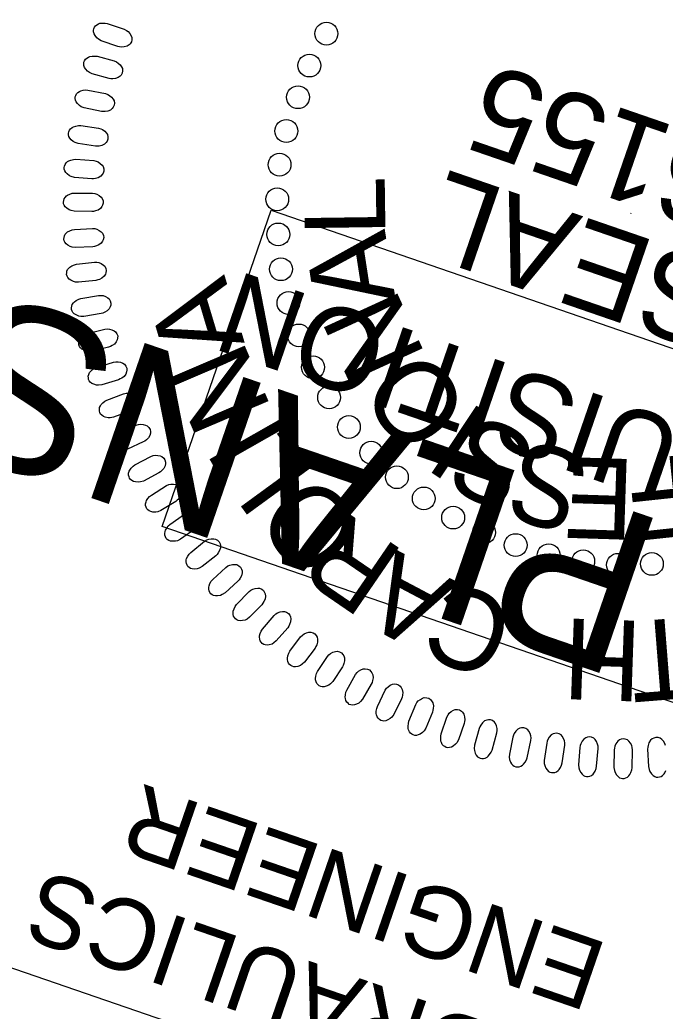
# Model space of a CAD drawing. Extents: x 479650 to 481768, y 492454 to 494037.
# Drawn here: x 479711.7 to 479757, y 493041.5 to 493111.2 of the extents above; entities that cross this region are included whole.
import ezdxf

# ---------------------------------------------------------------- set-up
doc = ezdxf.new("R2010")
doc.units = 0
for name, color, linetype in [('Sheet PE Seal Cell', 7, 'Continuous'), ('Sheet Plan CELL', 7, 'Continuous'), ('Sheet Sticker Incomplete CELL', 7, 'Continuous')]:
    doc.layers.add(name, color=color, linetype=linetype)

msp = doc.modelspace()

# ---------------------------------------------------------------- linework, layer by layer
at = {"layer": 'Sheet PE Seal Cell'}
msp.add_line((479754.607, 493097.561), (479754.623, 493097.605), dxfattribs=at)
for points in [[(479718.58, 493109.285), (479717.42, 493109.686), (479717.225, 493109.792), (479717.11, 493109.887), (479716.986, 493110.049), (479716.914, 493110.176), (479716.875, 493110.308), (479716.872, 493110.42), (479716.89, 493110.533), (479716.945, 493110.632), (479717.012, 493110.735), (479717.103, 493110.815), (479717.231, 493110.881), (479717.326, 493110.912), (479717.49, 493110.927), (479717.679, 493110.925), (479717.837, 493110.894), (479719.028, 493110.491), (479719.18, 493110.415), (479719.298, 493110.326), (479719.419, 493110.189), (479719.515, 493110.039), (479719.559, 493109.921), (479719.564, 493109.752), (479719.534, 493109.605), (479719.447, 493109.476), (479719.366, 493109.394), (479719.231, 493109.306), (479719.031, 493109.249), (479718.839, 493109.243), (479718.707, 493109.257)], [(479717.962, 493107.033), (479716.779, 493107.36), (479716.578, 493107.455), (479716.457, 493107.542), (479716.323, 493107.695), (479716.244, 493107.818), (479716.197, 493107.948), (479716.186, 493108.059), (479716.197, 493108.172), (479716.246, 493108.275), (479716.306, 493108.382), (479716.392, 493108.467), (479716.516, 493108.542), (479716.609, 493108.578), (479716.771, 493108.603), (479716.96, 493108.613), (479717.119, 493108.592), (479718.333, 493108.265), (479718.49, 493108.198), (479718.613, 493108.117), (479718.743, 493107.989), (479718.847, 493107.844), (479718.899, 493107.729), (479718.915, 493107.562), (479718.894, 493107.412), (479718.816, 493107.279), (479718.74, 493107.191), (479718.61, 493107.095), (479718.415, 493107.025), (479718.223, 493107.008), (479718.091, 493107.014)], [(479717.422, 493104.718), (479716.221, 493104.97), (479716.014, 493105.052), (479715.888, 493105.131), (479715.745, 493105.276), (479715.657, 493105.393), (479715.602, 493105.519), (479715.584, 493105.63), (479715.588, 493105.743), (479715.631, 493105.849), (479715.685, 493105.961), (479715.764, 493106.051), (479715.884, 493106.132), (479715.974, 493106.174), (479716.134, 493106.21), (479716.323, 493106.232), (479716.483, 493106.221), (479717.715, 493105.971), (479717.876, 493105.914), (479718.003, 493105.841), (479718.141, 493105.721), (479718.255, 493105.582), (479718.313, 493105.471), (479718.34, 493105.305), (479718.328, 493105.154), (479718.258, 493105.017), (479718.188, 493104.925), (479718.064, 493104.82), (479717.874, 493104.738), (479717.685, 493104.709), (479717.551, 493104.707)], [(479717.003, 493102.283), (479715.79, 493102.458), (479715.578, 493102.527), (479715.447, 493102.598), (479715.295, 493102.734), (479715.201, 493102.845), (479715.137, 493102.968), (479715.113, 493103.077), (479715.109, 493103.191), (479715.145, 493103.299), (479715.192, 493103.413), (479715.266, 493103.508), (479715.38, 493103.597), (479715.467, 493103.645), (479715.625, 493103.69), (479715.812, 493103.724), (479715.972, 493103.723), (479717.217, 493103.551), (479717.382, 493103.504), (479717.513, 493103.44), (479717.658, 493103.328), (479717.781, 493103.197), (479717.846, 493103.09), (479717.883, 493102.925), (479717.881, 493102.775), (479717.82, 493102.633), (479717.756, 493102.536), (479717.639, 493102.425), (479717.454, 493102.331), (479717.266, 493102.289), (479717.134, 493102.279)], [(479716.751, 493099.985), (479715.529, 493100.085), (479715.313, 493100.139), (479715.178, 493100.202), (479715.017, 493100.328), (479714.916, 493100.434), (479714.846, 493100.552), (479714.815, 493100.659), (479714.804, 493100.773), (479714.832, 493100.883), (479714.872, 493101), (479714.94, 493101.099), (479715.048, 493101.195), (479715.132, 493101.249), (479715.287, 493101.303), (479715.471, 493101.349), (479715.632, 493101.358), (479716.884, 493101.264), (479717.052, 493101.228), (479717.187, 493101.172), (479717.339, 493101.07), (479717.469, 493100.947), (479717.541, 493100.844), (479717.588, 493100.683), (479717.596, 493100.532), (479717.544, 493100.386), (479717.486, 493100.286), (479717.376, 493100.167), (479717.198, 493100.062), (479717.013, 493100.009), (479716.881, 493099.99)], [(479716.748, 493097.688), (479715.521, 493097.71), (479715.302, 493097.752), (479715.163, 493097.806), (479714.996, 493097.922), (479714.888, 493098.02), (479714.81, 493098.134), (479714.772, 493098.239), (479714.754, 493098.352), (479714.776, 493098.464), (479714.808, 493098.583), (479714.87, 493098.686), (479714.972, 493098.789), (479715.052, 493098.848), (479715.204, 493098.912), (479715.384, 493098.969), (479715.544, 493098.989), (479716.801, 493098.973), (479716.969, 493098.948), (479717.108, 493098.9), (479717.266, 493098.808), (479717.404, 493098.694), (479717.482, 493098.594), (479717.539, 493098.436), (479717.556, 493098.287), (479717.513, 493098.138), (479717.462, 493098.034), (479717.36, 493097.909), (479717.189, 493097.792), (479717.007, 493097.728), (479716.877, 493097.701)], [(479716.82, 493095.215), (479715.594, 493095.16), (479715.374, 493095.188), (479715.232, 493095.233), (479715.058, 493095.338), (479714.944, 493095.431), (479714.859, 493095.539), (479714.814, 493095.642), (479714.789, 493095.753), (479714.805, 493095.866), (479714.829, 493095.987), (479714.883, 493096.093), (479714.979, 493096.203), (479715.056, 493096.266), (479715.202, 493096.34), (479715.379, 493096.408), (479715.537, 493096.437), (479716.792, 493096.501), (479716.962, 493096.487), (479717.104, 493096.448), (479717.268, 493096.365), (479717.412, 493096.26), (479717.496, 493096.166), (479717.563, 493096.012), (479717.589, 493095.863), (479717.556, 493095.712), (479717.511, 493095.605), (479717.418, 493095.474), (479717.253, 493095.347), (479717.077, 493095.272), (479716.949, 493095.236)], [(479717.042, 493092.853), (479715.822, 493092.721), (479715.601, 493092.735), (479715.456, 493092.771), (479715.275, 493092.865), (479715.156, 493092.95), (479715.064, 493093.053), (479715.013, 493093.152), (479714.981, 493093.262), (479714.989, 493093.376), (479715.007, 493093.498), (479715.054, 493093.608), (479715.142, 493093.723), (479715.215, 493093.791), (479715.357, 493093.874), (479715.529, 493093.952), (479715.685, 493093.992), (479716.934, 493094.134), (479717.105, 493094.13), (479717.248, 493094.101), (479717.416, 493094.029), (479717.567, 493093.932), (479717.657, 493093.844), (479717.734, 493093.694), (479717.77, 493093.548), (479717.746, 493093.395), (479717.707, 493093.286), (479717.622, 493093.148), (479717.466, 493093.012), (479717.295, 493092.925), (479717.169, 493092.882)], [(479717.411, 493090.523), (479716.201, 493090.315), (479715.979, 493090.315), (479715.833, 493090.342), (479715.646, 493090.423), (479715.522, 493090.501), (479715.424, 493090.598), (479715.367, 493090.695), (479715.328, 493090.801), (479715.329, 493090.915), (479715.338, 493091.038), (479715.379, 493091.151), (479715.46, 493091.272), (479715.528, 493091.344), (479715.664, 493091.436), (479715.831, 493091.525), (479715.985, 493091.574), (479717.222, 493091.795), (479717.393, 493091.802), (479717.538, 493091.781), (479717.71, 493091.719), (479717.866, 493091.633), (479717.962, 493091.551), (479718.048, 493091.406), (479718.093, 493091.262), (479718.079, 493091.108), (479718.048, 493090.996), (479717.971, 493090.854), (479717.824, 493090.708), (479717.658, 493090.611), (479717.535, 493090.559)], [(479717.935, 493088.174), (479716.742, 493087.89), (479716.519, 493087.876), (479716.371, 493087.894), (479716.181, 493087.964), (479716.051, 493088.033), (479715.948, 493088.124), (479715.885, 493088.217), (479715.839, 493088.321), (479715.833, 493088.435), (479715.834, 493088.558), (479715.868, 493088.674), (479715.941, 493088.799), (479716.005, 493088.875), (479716.135, 493088.976), (479716.296, 493089.075), (479716.446, 493089.134), (479717.666, 493089.432), (479717.836, 493089.449), (479717.983, 493089.437), (479718.159, 493089.387), (479718.321, 493089.31), (479718.421, 493089.234), (479718.516, 493089.096), (479718.569, 493088.955), (479718.565, 493088.8), (479718.541, 493088.687), (479718.473, 493088.54), (479718.336, 493088.384), (479718.176, 493088.277), (479718.057, 493088.218)], [(479718.625, 493085.878), (479717.452, 493085.52), (479717.231, 493085.492), (479717.082, 493085.501), (479716.887, 493085.559), (479716.754, 493085.62), (479716.645, 493085.703), (479716.576, 493085.792), (479716.524, 493085.894), (479716.511, 493086.007), (479716.505, 493086.129), (479716.531, 493086.247), (479716.596, 493086.376), (479716.655, 493086.457), (479716.779, 493086.565), (479716.933, 493086.674), (479717.079, 493086.743), (479718.279, 493087.117), (479718.447, 493087.144), (479718.594, 493087.142), (479718.772, 493087.103), (479718.939, 493087.036), (479719.044, 493086.967), (479719.147, 493086.834), (479719.21, 493086.697), (479719.215, 493086.542), (479719.198, 493086.428), (479719.14, 493086.277), (479719.012, 493086.113), (479718.86, 493085.996), (479718.745, 493085.93)], [(479719.412, 493083.679), (479718.264, 493083.248), (479718.045, 493083.206), (479717.896, 493083.206), (479717.698, 493083.251), (479717.561, 493083.304), (479717.447, 493083.381), (479717.373, 493083.465), (479717.314, 493083.563), (479717.294, 493083.675), (479717.28, 493083.797), (479717.299, 493083.917), (479717.356, 493084.049), (479717.409, 493084.133), (479717.526, 493084.249), (479717.673, 493084.368), (479717.814, 493084.445), (479718.988, 493084.893), (479719.155, 493084.932), (479719.302, 493084.939), (479719.482, 493084.911), (479719.653, 493084.855), (479719.762, 493084.792), (479719.873, 493084.667), (479719.944, 493084.533), (479719.959, 493084.38), (479719.949, 493084.264), (479719.9, 493084.11), (479719.784, 493083.939), (479719.639, 493083.812), (479719.528, 493083.739)], [(479720.367, 493081.503), (479719.248, 493081.001), (479719.033, 493080.945), (479718.884, 493080.935), (479718.683, 493080.968), (479718.544, 493081.012), (479718.425, 493081.081), (479718.345, 493081.161), (479718.281, 493081.255), (479718.254, 493081.366), (479718.232, 493081.487), (479718.244, 493081.607), (479718.292, 493081.743), (479718.341, 493081.83), (479718.449, 493081.953), (479718.588, 493082.081), (479718.725, 493082.167), (479719.868, 493082.688), (479720.032, 493082.737), (479720.178, 493082.753), (479720.36, 493082.737), (479720.533, 493082.692), (479720.646, 493082.636), (479720.765, 493082.517), (479720.845, 493082.389), (479720.87, 493082.236), (479720.867, 493082.12), (479720.828, 493081.963), (479720.722, 493081.785), (479720.585, 493081.65), (479720.479, 493081.57)], [(479721.465, 493079.334), (479720.379, 493078.762), (479720.168, 493078.693), (479720.02, 493078.674), (479719.818, 493078.694), (479719.675, 493078.729), (479719.553, 493078.791), (479719.468, 493078.865), (479719.398, 493078.955), (479719.364, 493079.063), (479719.335, 493079.183), (479719.339, 493079.304), (479719.378, 493079.443), (479719.421, 493079.534), (479719.522, 493079.662), (479719.653, 493079.799), (479719.783, 493079.893), (479720.892, 493080.485), (479721.053, 493080.544), (479721.197, 493080.569), (479721.38, 493080.564), (479721.555, 493080.531), (479721.672, 493080.482), (479721.798, 493080.371), (479721.885, 493080.248), (479721.919, 493080.097), (479721.924, 493079.981), (479721.895, 493079.822), (479721.801, 493079.637), (479721.674, 493079.494), (479721.572, 493079.408)], [(479722.647, 493077.325), (479721.599, 493076.687), (479721.393, 493076.604), (479721.246, 493076.576), (479721.043, 493076.583), (479720.899, 493076.609), (479720.772, 493076.664), (479720.684, 493076.732), (479720.608, 493076.818), (479720.567, 493076.923), (479720.53, 493077.042), (479720.527, 493077.162), (479720.558, 493077.303), (479720.594, 493077.396), (479720.688, 493077.531), (479720.809, 493077.676), (479720.934, 493077.778), (479722.003, 493078.438), (479722.16, 493078.508), (479722.302, 493078.542), (479722.485, 493078.548), (479722.663, 493078.526), (479722.782, 493078.484), (479722.914, 493078.381), (479723.009, 493078.264), (479723.053, 493078.115), (479723.065, 493078), (479723.045, 493077.84), (479722.963, 493077.65), (479722.845, 493077.498), (479722.749, 493077.406)], [(479723.977, 493075.369), (479722.972, 493074.666), (479722.77, 493074.571), (479722.626, 493074.533), (479722.423, 493074.528), (479722.277, 493074.545), (479722.148, 493074.591), (479722.054, 493074.654), (479721.974, 493074.735), (479721.926, 493074.838), (479721.882, 493074.953), (479721.871, 493075.073), (479721.893, 493075.216), (479721.924, 493075.311), (479722.008, 493075.452), (479722.121, 493075.603), (479722.239, 493075.713), (479723.264, 493076.44), (479723.416, 493076.518), (479723.556, 493076.562), (479723.738, 493076.58), (479723.917, 493076.568), (479724.038, 493076.534), (479724.177, 493076.44), (479724.279, 493076.328), (479724.332, 493076.183), (479724.351, 493076.069), (479724.343, 493075.908), (479724.272, 493075.712), (479724.163, 493075.554), (479724.074, 493075.455)], [(479725.452, 493073.514), (479724.494, 493072.749), (479724.299, 493072.641), (479724.157, 493072.596), (479723.955, 493072.577), (479723.808, 493072.585), (479723.676, 493072.623), (479723.58, 493072.68), (479723.494, 493072.755), (479723.439, 493072.855), (479723.389, 493072.967), (479723.37, 493073.086), (479723.383, 493073.23), (479723.408, 493073.327), (479723.483, 493073.473), (479723.586, 493073.632), (479723.697, 493073.749), (479724.674, 493074.538), (479724.821, 493074.626), (479724.958, 493074.678), (479725.139, 493074.707), (479725.318, 493074.707), (479725.441, 493074.681), (479725.586, 493074.595), (479725.694, 493074.49), (479725.756, 493074.349), (479725.782, 493074.236), (479725.784, 493074.074), (479725.726, 493073.875), (479725.627, 493073.711), (479725.544, 493073.606)], [(479727.012, 493071.723), (479726.104, 493070.9), (479725.916, 493070.78), (479725.777, 493070.725), (479725.576, 493070.695), (479725.43, 493070.693), (479725.295, 493070.722), (479725.195, 493070.773), (479725.105, 493070.843), (479725.045, 493070.939), (479724.987, 493071.048), (479724.961, 493071.166), (479724.964, 493071.31), (479724.984, 493071.408), (479725.049, 493071.558), (479725.142, 493071.723), (479725.245, 493071.847), (479726.172, 493072.696), (479726.312, 493072.793), (479726.446, 493072.854), (479726.624, 493072.895), (479726.803, 493072.905), (479726.927, 493072.887), (479727.077, 493072.811), (479727.192, 493072.713), (479727.264, 493072.576), (479727.297, 493072.464), (479727.308, 493072.303), (479727.263, 493072.101), (479727.175, 493071.931), (479727.098, 493071.821)], [(479728.69, 493070.071), (479727.834, 493069.192), (479727.655, 493069.061), (479727.52, 493068.998), (479727.321, 493068.954), (479727.175, 493068.943), (479727.039, 493068.965), (479726.936, 493069.009), (479726.842, 493069.073), (479726.776, 493069.166), (479726.71, 493069.27), (479726.677, 493069.386), (479726.672, 493069.531), (479726.684, 493069.629), (479726.741, 493069.784), (479726.823, 493069.954), (479726.918, 493070.084), (479727.79, 493070.99), (479727.924, 493071.095), (479728.054, 493071.164), (479728.229, 493071.216), (479728.407, 493071.238), (479728.532, 493071.227), (479728.687, 493071.161), (479728.807, 493071.07), (479728.886, 493070.938), (479728.927, 493070.829), (479728.948, 493070.669), (479728.916, 493070.464), (479728.839, 493070.288), (479728.77, 493070.175)], [(479730.505, 493068.458), (479729.706, 493067.527), (479729.535, 493067.385), (479729.404, 493067.313), (479729.208, 493067.257), (479729.063, 493067.237), (479728.926, 493067.25), (479728.821, 493067.288), (479728.723, 493067.345), (479728.651, 493067.433), (479728.579, 493067.534), (479728.539, 493067.648), (479728.524, 493067.792), (479728.531, 493067.891), (479728.577, 493068.048), (479728.648, 493068.224), (479728.735, 493068.36), (479729.548, 493069.318), (479729.676, 493069.432), (479729.801, 493069.509), (479729.973, 493069.571), (479730.149, 493069.605), (479730.274, 493069.602), (479730.433, 493069.545), (479730.559, 493069.462), (479730.646, 493069.335), (479730.694, 493069.229), (479730.725, 493069.071), (479730.705, 493068.864), (479730.64, 493068.684), (479730.577, 493068.566)], [(479732.424, 493067.02), (479731.685, 493066.04), (479731.523, 493065.887), (479731.397, 493065.808), (479731.206, 493065.74), (479731.062, 493065.711), (479730.925, 493065.714), (479730.817, 493065.746), (479730.715, 493065.797), (479730.638, 493065.881), (479730.561, 493065.977), (479730.513, 493066.088), (479730.49, 493066.23), (479730.49, 493066.33), (479730.526, 493066.49), (479730.587, 493066.669), (479730.665, 493066.81), (479731.416, 493067.817), (479731.535, 493067.94), (479731.656, 493068.024), (479731.823, 493068.098), (479731.997, 493068.141), (479732.122, 493068.147), (479732.284, 493068.1), (479732.415, 493068.025), (479732.511, 493067.904), (479732.564, 493067.801), (479732.606, 493067.645), (479732.599, 493067.438), (479732.545, 493067.253), (479732.49, 493067.132)], [(479734.349, 493065.699), (479733.673, 493064.675), (479733.521, 493064.513), (479733.4, 493064.424), (479733.213, 493064.344), (479733.072, 493064.307), (479732.934, 493064.302), (479732.825, 493064.326), (479732.72, 493064.371), (479732.638, 493064.45), (479732.554, 493064.541), (479732.5, 493064.648), (479732.468, 493064.789), (479732.462, 493064.888), (479732.488, 493065.051), (479732.537, 493065.233), (479732.606, 493065.379), (479733.292, 493066.432), (479733.405, 493066.56), (479733.519, 493066.652), (479733.681, 493066.736), (479733.852, 493066.791), (479733.977, 493066.804), (479734.141, 493066.768), (479734.277, 493066.702), (479734.379, 493066.586), (479734.439, 493066.487), (479734.49, 493066.334), (479734.497, 493066.126), (479734.454, 493065.94), (479734.408, 493065.815)], [(479736.374, 493064.499), (479735.764, 493063.436), (479735.622, 493063.264), (479735.507, 493063.169), (479735.326, 493063.078), (479735.187, 493063.031), (479735.05, 493063.017), (479734.94, 493063.035), (479734.832, 493063.073), (479734.745, 493063.146), (479734.656, 493063.232), (479734.595, 493063.336), (479734.554, 493063.474), (479734.541, 493063.573), (479734.558, 493063.736), (479734.595, 493063.922), (479734.655, 493064.072), (479735.273, 493065.166), (479735.377, 493065.301), (479735.486, 493065.4), (479735.643, 493065.494), (479735.81, 493065.559), (479735.934, 493065.58), (479736.099, 493065.554), (479736.239, 493065.497), (479736.349, 493065.388), (479736.415, 493065.293), (479736.475, 493065.143), (479736.495, 493064.936), (479736.464, 493064.747), (479736.425, 493064.62)], [(479738.492, 493063.467), (479737.95, 493062.366), (479737.82, 493062.186), (479737.711, 493062.084), (479737.536, 493061.981), (479737.4, 493061.926), (479737.264, 493061.904), (479737.153, 493061.914), (479737.043, 493061.946), (479736.951, 493062.014), (479736.858, 493062.093), (479736.79, 493062.193), (479736.74, 493062.329), (479736.722, 493062.427), (479736.727, 493062.591), (479736.754, 493062.778), (479736.804, 493062.931), (479737.352, 493064.062), (479737.448, 493064.204), (479737.549, 493064.309), (479737.7, 493064.413), (479737.862, 493064.488), (479737.985, 493064.517), (479738.152, 493064.502), (479738.295, 493064.454), (479738.412, 493064.351), (479738.484, 493064.261), (479738.554, 493064.115), (479738.586, 493063.91), (479738.567, 493063.719), (479738.536, 493063.589)], [(479740.669, 493062.532), (479740.197, 493061.399), (479740.078, 493061.211), (479739.976, 493061.102), (479739.807, 493060.989), (479739.675, 493060.925), (479739.541, 493060.895), (479739.429, 493060.898), (479739.318, 493060.923), (479739.222, 493060.985), (479739.123, 493061.058), (479739.05, 493061.154), (479738.991, 493061.286), (479738.967, 493061.382), (479738.962, 493061.547), (479738.976, 493061.735), (479739.017, 493061.891), (479739.494, 493063.054), (479739.579, 493063.202), (479739.675, 493063.313), (479739.819, 493063.426), (479739.976, 493063.512), (479740.097, 493063.548), (479740.265, 493063.543), (479740.41, 493063.504), (479740.533, 493063.41), (479740.61, 493063.323), (479740.689, 493063.182), (479740.734, 493062.98), (479740.727, 493062.788), (479740.705, 493062.657)], [(479742.891, 493061.738), (479742.491, 493060.579), (479742.384, 493060.383), (479742.288, 493060.268), (479742.128, 493060.145), (479742, 493060.072), (479741.868, 493060.034), (479741.756, 493060.03), (479741.643, 493060.048), (479741.544, 493060.103), (479741.441, 493060.17), (479741.361, 493060.261), (479741.295, 493060.389), (479741.264, 493060.485), (479741.25, 493060.648), (479741.251, 493060.837), (479741.282, 493060.995), (479741.685, 493062.185), (479741.761, 493062.339), (479741.849, 493062.456), (479741.986, 493062.577), (479742.138, 493062.673), (479742.256, 493062.717), (479742.424, 493062.722), (479742.571, 493062.692), (479742.699, 493062.606), (479742.782, 493062.525), (479742.87, 493062.389), (479742.928, 493062.189), (479742.933, 493061.998), (479742.919, 493061.865)], [(479743.948, 493061.383), (479743.622, 493060.201), (479743.6, 493059.979), (479743.613, 493059.831), (479743.676, 493059.637), (479743.74, 493059.506), (479743.827, 493059.399), (479743.917, 493059.333), (479744.02, 493059.284), (479744.134, 493059.274), (479744.257, 493059.27), (479744.374, 493059.3), (479744.501, 493059.369), (479744.579, 493059.43), (479744.685, 493059.556), (479744.79, 493059.713), (479744.854, 493059.86), (479745.195, 493061.07), (479745.219, 493061.239), (479745.213, 493061.386), (479745.169, 493061.564), (479745.098, 493061.728), (479745.026, 493061.831), (479744.89, 493061.931), (479744.751, 493061.99), (479744.596, 493061.991), (479744.482, 493061.97), (479744.333, 493061.908), (479744.173, 493061.776), (479744.06, 493061.621), (479743.997, 493061.504)], [(479746.319, 493060.781), (479746.068, 493059.58), (479746.059, 493059.357), (479746.082, 493059.21), (479746.157, 493059.021), (479746.23, 493058.894), (479746.323, 493058.793), (479746.418, 493058.732), (479746.523, 493058.69), (479746.637, 493058.687), (479746.76, 493058.691), (479746.875, 493058.728), (479746.998, 493058.804), (479747.072, 493058.87), (479747.169, 493059.003), (479747.264, 493059.166), (479747.319, 493059.318), (479747.584, 493060.546), (479747.597, 493060.717), (479747.582, 493060.863), (479747.527, 493061.037), (479747.445, 493061.197), (479747.366, 493061.295), (479747.225, 493061.386), (479747.083, 493061.436), (479746.929, 493061.427), (479746.816, 493061.4), (479746.671, 493061.328), (479746.519, 493061.187), (479746.417, 493061.025), (479746.361, 493060.905)], [(479748.691, 493060.353), (479748.515, 493059.14), (479748.521, 493058.917), (479748.552, 493058.771), (479748.639, 493058.587), (479748.719, 493058.465), (479748.819, 493058.369), (479748.917, 493058.315), (479749.025, 493058.279), (479749.139, 493058.283), (479749.261, 493058.296), (479749.374, 493058.339), (479749.492, 493058.423), (479749.562, 493058.494), (479749.65, 493058.632), (479749.735, 493058.801), (479749.78, 493058.956), (479749.967, 493060.198), (479749.97, 493060.37), (479749.945, 493060.514), (479749.879, 493060.685), (479749.788, 493060.839), (479749.703, 493060.932), (479749.556, 493061.014), (479749.411, 493061.055), (479749.258, 493061.037), (479749.147, 493061.002), (479749.007, 493060.922), (479748.864, 493060.771), (479748.772, 493060.603), (479748.724, 493060.479)], [(479751.024, 493060.048), (479750.925, 493058.826), (479750.945, 493058.604), (479750.985, 493058.46), (479751.084, 493058.283), (479751.172, 493058.166), (479751.277, 493058.077), (479751.378, 493058.028), (479751.488, 493058), (479751.602, 493058.01), (479751.723, 493058.031), (479751.832, 493058.082), (479751.945, 493058.173), (479752.011, 493058.247), (479752.09, 493058.391), (479752.164, 493058.565), (479752.199, 493058.722), (479752.308, 493059.974), (479752.3, 493060.145), (479752.266, 493060.288), (479752.189, 493060.454), (479752.089, 493060.603), (479751.998, 493060.689), (479751.847, 493060.763), (479751.699, 493060.794), (479751.547, 493060.767), (479751.439, 493060.725), (479751.304, 493060.636), (479751.171, 493060.477), (479751.09, 493060.303), (479751.049, 493060.177)], [(479753.433, 493059.875), (479753.411, 493058.649), (479753.444, 493058.429), (479753.494, 493058.288), (479753.602, 493058.117), (479753.698, 493058.005), (479753.808, 493057.923), (479753.913, 493057.881), (479754.024, 493057.859), (479754.137, 493057.877), (479754.256, 493057.905), (479754.362, 493057.963), (479754.469, 493058.061), (479754.53, 493058.14), (479754.6, 493058.288), (479754.663, 493058.466), (479754.689, 493058.626), (479754.719, 493059.882), (479754.699, 493060.052), (479754.657, 493060.192), (479754.57, 493060.353), (479754.46, 493060.495), (479754.365, 493060.576), (479754.209, 493060.639), (479754.06, 493060.662), (479753.909, 493060.625), (479753.804, 493060.576), (479753.675, 493060.479), (479753.552, 493060.312), (479753.482, 493060.133), (479753.45, 493060.004)]]:
    msp.add_lwpolyline(points, close=True, dxfattribs=at)
msp.add_lwpolyline([(479757.032, 493060.186), (479756.981, 493060.323), (479756.884, 493060.479), (479756.766, 493060.613), (479756.666, 493060.689), (479756.506, 493060.742), (479756.355, 493060.754), (479756.208, 493060.707), (479756.106, 493060.653), (479755.983, 493060.548), (479755.871, 493060.374), (479755.812, 493060.191), (479755.788, 493060.06), (479755.779, 493059.93), (479755.834, 493058.704), (479755.882, 493058.487), (479755.939, 493058.35), (479756.059, 493058.185), (479756.161, 493058.08), (479756.277, 493058.006), (479756.383, 493057.97), (479756.496, 493057.956), (479756.608, 493057.981), (479756.726, 493058.016), (479756.828, 493058.08), (479756.928, 493058.185), (479756.984, 493058.267), (479757.044, 493058.42)], dxfattribs=at)
for centre in [(479733.223, 493110.185), (479732.028, 493107.942), (479731.23, 493105.717), (479730.412, 493103.344), (479729.934, 493100.981), (479729.77, 493098.551), (479729.844, 493096.081), (479730.031, 493093.638), (479730.56, 493091.264), (479731.291, 493088.989), (479732.287, 493086.749), (479733.411, 493084.634), (479734.799, 493082.554), (479736.367, 493080.749), (479738.174, 493079.03), (479740.06, 493077.537), (479742.123, 493076.193), (479744.291, 493075.151), (479746.51, 493074.259), (479748.832, 493073.542), (479751.257, 493073.127), (479753.698, 493072.876), (479756.078, 493072.939)]:
    msp.add_circle(centre, 0.801, dxfattribs=at)
at = {"layer": 'Sheet Plan CELL'}
msp.add_lwpolyline([(479780.521, 493020.65), (479685.983, 493053.209), (479722.622, 493159.589), (479817.172, 493127.026)], close=True, dxfattribs=at)
at = {"layer": 'Sheet Sticker Incomplete CELL'}
msp.add_lwpolyline([(479868.336, 493049.89), (479860.681, 493027.672), (479721.698, 493075.556), (479729.353, 493097.774)], close=True, dxfattribs=at)

# ---------------------------------------------------------------- texts
at = {"layer": 'Sheet PE Seal Cell'}
for s, height, rotation, p in [('46155', 6.2363, 160.9706, (479766.641, 493100.592)), ('SEAL', 6.2363, 160.9706, (479761.79, 493093.718)), ('L', 5.669, 90.8201, (479737.374, 493095.983)), ('A', 5.669, 98.75989, (479738.081, 493091.514)), ('A', 5.669, 106.66206, (479727.492, 493088.458)), ('N', 5.669, 114.63949, (479740.233, 493087.515)), ('N', 5.669, 113.15142, (479729.4, 493083.803)), ('O', 5.669, 130.51908, (479743.558, 493083.932)), ('I', 5.669, 146.39868, (479744.924, 493083.279)), ('I', 5.669, 119.64078, (479730.644, 493081.872)), ('L', 5.669, 126.13013, (479732.586, 493079.243)), ('S', 5.669, 154.33847, (479748.311, 493081.444)), ('S', 5.669, 162.27827, (479751.995, 493080.282)), ('E', 5.669, 178.15786, (479754.924, 493080.288)), ('F', 5.669, 186.09766, (479758.63, 493080.638)), ('O', 5.669, 132.61949, (479736.236, 493075.308)), ('R', 5.669, 145.5982, (479738.817, 493073.727)), ('A', 5.669, 152.08756, (479742.536, 493071.606)), ('C', 5.669, 158.57692, (479746.793, 493069.918)), ('H', 5.669, 178.04499, (479755.448, 493068.929)), ('T', 5.669, 184.53434, (479758.913, 493069.226))]:
    msp.add_text(s, height=height, rotation=rotation, dxfattribs=at).set_placement(p)
at = {"layer": 'Sheet Plan CELL'}
for s, p in [('ENGINEER', (479753.127, 493046.205)), ('HYDRAULICS', (479754.09, 493037.451))]:
    msp.add_text(s, height=5.0001, rotation=160.98924, dxfattribs=at).set_placement(p)
at = {"layer": 'Sheet Sticker Incomplete CELL'}
for s, height, p in [('DO NOT USE FOR R/W ACQUISITION', 5.76, (479855.254, 493049.373)), ('INCOMPLETE PLANS', 11.52, (479856.063, 493041.743))]:
    msp.add_text(s, height=height, rotation=160.98924, dxfattribs=at).set_placement(p)

doc.saveas('drawing.dxf')
